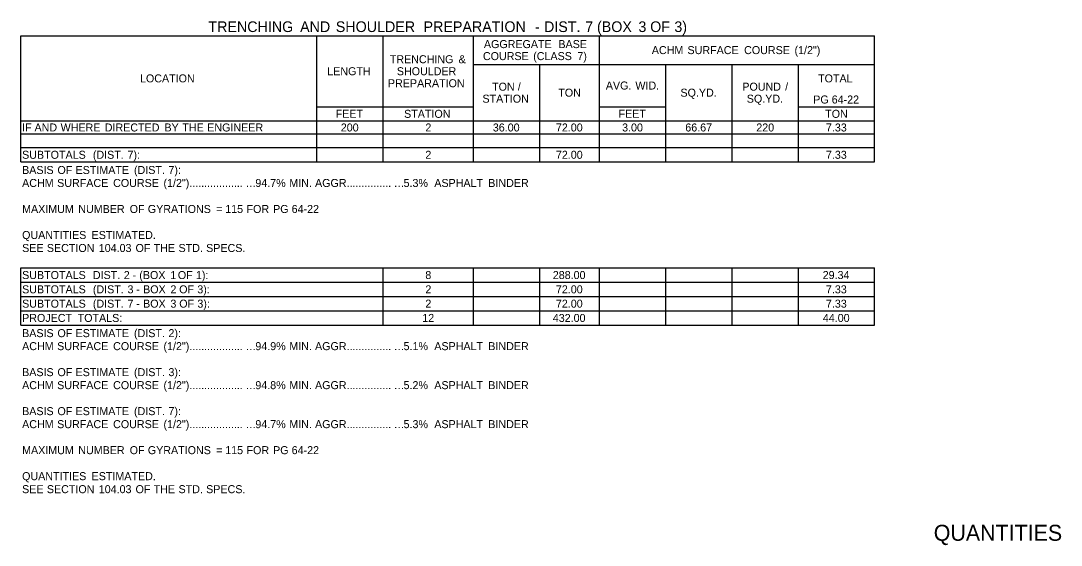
# Model space of a CAD drawing. Extents: x 544250 to 1930787, y -1948365 to 596640.
# Drawn here: x 546909 to 547689, y -1948344 to -1947951 of the extents above; entities that cross this region are included whole.
import ezdxf

# ---------------------------------------------------------------- set-up
doc = ezdxf.new("R2010")
doc.units = 0
doc.layers.add('Default', color=7, linetype='Continuous')
doc.layers.add('R_Border', color=7, linetype='Continuous')

msp = doc.modelspace()

# ---------------------------------------------------------------- linework, layer by layer
at = {"layer": 'Default'}
for p, q in [((546908.73, -1947962.26), (547548.82, -1947962.26)), ((546908.73, -1948056.83), (546908.73, -1947962.26)), ((546908.73, -1948056.83), (546908.73, -1947962.26)), ((547130.54, -1948056.83), (547130.54, -1947962.26)), ((547180.27, -1948056.83), (547180.27, -1947962.26)), ((547248.03, -1948056.83), (547248.03, -1947962.26)), ((547342.61, -1948056.83), (547342.61, -1947962.26)), ((547548.82, -1948056.83), (547548.82, -1947962.26)), ((547548.82, -1948056.83), (547548.82, -1947962.26)), ((547248.03, -1947983.71), (547548.82, -1947983.71)), ((547297.76, -1948056.83), (547297.76, -1947983.71)), ((547392.33, -1948056.83), (547392.33, -1947983.71)), ((547442.06, -1948056.83), (547442.06, -1947983.71)), ((547491.78, -1948056.83), (547491.78, -1947983.71)), ((547130.54, -1948015.4), (547248.03, -1948015.4)), ((547180.27, -1948046.11), (547180.27, -1948015.4)), ((547342.61, -1948015.4), (547392.33, -1948015.4)), ((547342.61, -1948026.12), (547342.61, -1948015.4)), ((547392.33, -1948046.11), (547392.33, -1948015.4)), ((547491.78, -1948015.4), (547548.82, -1948015.4)), ((546908.73, -1948026.12), (547491.78, -1948026.12)), ((547130.54, -1948056.83), (547130.54, -1948026.12)), ((547248.03, -1948026.12), (547392.33, -1948026.12)), ((547248.03, -1948046.11), (547248.03, -1948026.12)), ((547297.76, -1948046.11), (547297.76, -1948026.12)), ((547392.33, -1948026.12), (547548.82, -1948026.12)), ((547442.06, -1948046.11), (547442.06, -1948026.12)), ((547491.78, -1948026.12), (547548.82, -1948026.12)), ((547491.78, -1948046.11), (547491.78, -1948026.12)), ((546908.73, -1948035.87), (547548.82, -1948035.87)), ((546908.73, -1948046.11), (547548.82, -1948046.11)), ((546908.73, -1948046.11), (547548.82, -1948046.11)), ((546908.73, -1948056.83), (547548.82, -1948056.83)), ((546908.73, -1948136.3), (547548.82, -1948136.3)), ((546908.73, -1948136.3), (547548.82, -1948136.3)), ((546908.73, -1948179.2), (546908.73, -1948136.3)), ((546908.73, -1948179.2), (546908.73, -1948136.3)), ((547180.27, -1948179.2), (547180.27, -1948136.3)), ((547180.27, -1948179.2), (547180.27, -1948136.3)), ((547248.03, -1948179.2), (547248.03, -1948136.3)), ((547248.03, -1948179.2), (547248.03, -1948136.3)), ((547297.76, -1948179.2), (547297.76, -1948136.3)), ((547342.61, -1948179.2), (547342.61, -1948136.3)), ((547392.33, -1948179.2), (547392.33, -1948136.3)), ((547442.06, -1948179.2), (547442.06, -1948136.3)), ((547491.78, -1948179.2), (547491.78, -1948136.3)), ((547548.82, -1948179.2), (547548.82, -1948136.3)), ((547548.82, -1948179.2), (547548.82, -1948136.3)), ((546908.73, -1948147.02), (547548.82, -1948147.02)), ((546908.73, -1948157.75), (547548.82, -1948157.75)), ((546908.73, -1948168.47), (547548.82, -1948168.47)), ((546908.73, -1948179.2), (547548.82, -1948179.2))]:
    msp.add_line(p, q, dxfattribs=at)

# ---------------------------------------------------------------- texts
for s, height, p in [('TRENCHING', 8, (547049.37, -1947959.43)), (' AND', 8, (547115.15, -1947959.43)), (' SHOULDER', 8, (547141.92, -1947959.43)), (' PREPARATION', 8, (547207.7, -1947959.43)), (' -', 8, (547291.27, -1947959.43)), (' DIST.', 8, (547298.01, -1947959.43)), (' 7', 8, (547328.92, -1947959.43)), (' (BOX', 8, (547337.74, -1947959.43)), (' 3', 8, (547368.78, -1947959.43)), (' OF', 8, (547377.61, -1947959.43)), (' 3)', 8, (547395.72, -1947959.43)), ('AGGREGATE', 6, (547255.9, -1947971.48)), (' BASE', 6, (547309.53, -1947971.48)), ('ACHM', 6, (547381.78, -1947975.98)), (' SURFACE', 6, (547406.33, -1947975.98)), (' COURSE', 6, (547448.77, -1947975.98)), (' (1/2")', 6, (547486.55, -1947975.98)), ('TRENCHING', 6, (547185.36, -1947982.83)), (' &', 6, (547234.69, -1947982.83)), ('COURSE', 6, (547255.19, -1947980.48)), (' (CLASS', 6, (547290.65, -1947980.48)), (' 7)', 6, (547323.77, -1947980.48)), ('LENGTH', 6, (547138.49, -1947991.83)), ('SHOULDER', 6, (547190.65, -1947991.83)), ('LOCATION', 6, (546998.08, -1947997.19)), ('PREPARATION', 6, (547183.97, -1948000.83)), ('AVG.', 6, (547347.32, -1948002.55)), (' WID.', 6, (547367.24, -1948002.55)), ('TOTAL', 6, (547506.45, -1947997.19)), ('TON', 6, (547262.05, -1948003.41)), (' /', 6, (547279.07, -1948003.41)), ('TON', 6, (547311.67, -1948007.91)), ('SQ.YD.', 6, (547403.27, -1948007.91)), ('POUND', 6, (547449.66, -1948003.41)), (' /', 6, (547479.52, -1948003.41)), ('STATION', 6, (547254.83, -1948012.41)), ('SQ.YD.', 6, (547453, -1948012.41)), ('PG', 6, (547502.83, -1948013.03)), (' 64-22', 6, (547514.43, -1948013.03)), ('FEET', 6, (547144.78, -1948023.76)), ('STATION', 6, (547196.09, -1948023.76)), ('FEET', 6, (547356.84, -1948023.76)), ('TON', 6, (547511.79, -1948023.76)), ('IF', 6, (546909.71, -1948034)), (' AND', 6, (546916.77, -1948034)), (' WHERE', 6, (546936.35, -1948034)), (' DIRECTED', 6, (546969.44, -1948034)), (' BY', 6, (547014.18, -1948034)), (' THE', 6, (547027.63, -1948034)), (' ENGINEER', 6, (547046.27, -1948034)), ('200', 6, (547148.62, -1948034)), ('2', 6, (547212.04, -1948034)), ('36.00', 6, (547262.61, -1948034)), ('72.00', 6, (547309.9, -1948034)), ('3.00', 6, (547359.52, -1948034)), ('66.67', 6, (547406.9, -1948034)), ('220', 6, (547460.13, -1948034)), ('7.33', 6, (547512.34, -1948034)), ('SUBTOTALS', 6, (546909.71, -1948054.47)), (' (DIST.', 6, (546960.53, -1948054.47)), (' 7):', 6, (546986.5, -1948054.47)), ('2', 6, (547212.03, -1948054.47)), ('72.00', 6, (547309.9, -1948054.47)), ('7.33', 6, (547512.33, -1948054.47)), ('BASIS', 6, (546909.71, -1948065.87)), (' OF', 6, (546933.97, -1948065.87)), (' ESTIMATE', 6, (546947.55, -1948065.87)), (' (DIST.', 6, (546991.36, -1948065.87)), (' 7):', 6, (547017.17, -1948065.87)), ('ACHM', 6, (546909.71, -1948075.62)), (' SURFACE', 6, (546933.76, -1948075.62)), (' COURSE', 6, (546975.71, -1948075.62)), (' (1/2")..................', 6, (547013.46, -1948075.62)), ('94.7%', 6, (547084.56, -1948075.62)), (' MIN.', 6, (547107.8, -1948075.62)), (' AGGR...............', 6, (547127.09, -1948075.62)), ('5.3%', 6, (547195.69, -1948075.62)), ('  ASPHALT', 6, (547214.27, -1948075.62)), (' BINDER', 6, (547256.97, -1948075.62)), ('…', 6, (547077.16, -1948075.62)), ('…', 6, (547188.29, -1948075.62)), ('MAXIMUM', 6, (546909.71, -1948095.12)), (' NUMBER', 6, (546949.59, -1948095.12)), (' OF', 6, (546988.14, -1948095.12)), (' GYRATIONS', 6, (547001.73, -1948095.12)), (' 115', 6, (547059.75, -1948095.12)), (' FOR', 6, (547075.73, -1948095.12)), (' PG', 6, (547095.64, -1948095.12)), (' 64-22', 6, (547109.55, -1948095.12)), (' =', 6, (547053, -1948095.12)), ('QUANTITIES', 6, (546909.71, -1948114.62)), (' ESTIMATED.', 6, (546959.58, -1948114.62)), ('SEE', 6, (546909.71, -1948124.37)), (' SECTION', 6, (546926.04, -1948124.37)), (' 104.03', 6, (546964.95, -1948124.37)), (' OF', 6, (546992.52, -1948124.37)), (' THE', 6, (547006.11, -1948124.37)), (' STD.', 6, (547024.76, -1948124.37)), (' SPECS.', 6, (547045.45, -1948124.37)), ('SUBTOTALS', 6, (546909.71, -1948144.66)), (' DIST.', 6, (546960.53, -1948144.66)), (' 2', 6, (546983.71, -1948144.66)), (' -', 6, (546990.28, -1948144.66)), (' (BOX', 6, (546995.33, -1948144.66)), (' 1', 6, (547018.61, -1948144.66)), (' OF', 6, (547024.24, -1948144.66)), (' 1):', 6, (547037.82, -1948144.66)), ('8', 6, (547212.01, -1948144.66)), ('288.00', 6, (547307.57, -1948144.66)), ('29.34', 6, (547509.91, -1948144.66)), ('SUBTOTALS', 6, (546909.71, -1948155.38)), (' (DIST.', 6, (546960.53, -1948155.38)), (' 3', 6, (546986.5, -1948155.38)), (' BOX', 6, (546998.18, -1948155.38)), (' 2', 6, (547018.67, -1948155.38)), (' OF', 6, (547025.24, -1948155.38)), (' 3):', 6, (547038.82, -1948155.38)), ('2', 6, (547212.03, -1948155.38)), ('72.00', 6, (547309.9, -1948155.38)), ('7.33', 6, (547512.33, -1948155.38)), ('SUBTOTALS', 6, (546909.71, -1948166.11)), (' (DIST.', 6, (546960.53, -1948166.11)), (' 7', 6, (546986.5, -1948166.11)), (' -', 6, (546993.13, -1948155.38)), (' BOX', 6, (546998.17, -1948166.11)), (' 3', 6, (547018.66, -1948166.11)), (' OF', 6, (547025.29, -1948166.11)), (' 3):', 6, (547038.87, -1948166.11)), ('2', 6, (547212.03, -1948166.11)), ('72.00', 6, (547309.9, -1948166.11)), ('7.33', 6, (547512.33, -1948166.11)), (' -', 6, (546993.12, -1948166.11)), ('PROJECT', 6, (546909.71, -1948176.83)), (' TOTALS:', 6, (546949.13, -1948176.83)), ('12', 6, (547209.7, -1948176.83)), ('432.00', 6, (547307.57, -1948176.83)), ('44.00', 6, (547510.02, -1948176.83)), ('BASIS', 6, (546909.71, -1948188.23)), (' OF', 6, (546933.97, -1948188.23)), (' ESTIMATE', 6, (546947.55, -1948188.23)), (' (DIST.', 6, (546991.36, -1948188.23)), (' 2):', 6, (547017.17, -1948188.23)), (' (1/2")..................', 6, (547013.46, -1948197.98)), ('ACHM', 6, (546909.71, -1948197.98)), (' SURFACE', 6, (546933.76, -1948197.98)), (' COURSE', 6, (546975.71, -1948197.98)), ('…', 6, (547077.16, -1948197.98)), ('94.9%', 6, (547084.56, -1948197.98)), (' MIN.', 6, (547107.8, -1948197.98)), (' AGGR...............', 6, (547127.09, -1948197.98)), ('…', 6, (547188.29, -1948197.98)), ('5.1%', 6, (547195.69, -1948197.98)), ('  ASPHALT', 6, (547214.27, -1948197.98)), (' BINDER', 6, (547256.97, -1948197.98)), ('BASIS', 6, (546909.71, -1948217.48)), (' OF', 6, (546933.97, -1948217.48)), (' ESTIMATE', 6, (546947.55, -1948217.48)), (' (DIST.', 6, (546991.36, -1948217.48)), (' 3):', 6, (547017.17, -1948217.48)), ('ACHM', 6, (546909.71, -1948227.23)), (' SURFACE', 6, (546933.76, -1948227.23)), (' COURSE', 6, (546975.71, -1948227.23)), (' (1/2")..................', 6, (547013.46, -1948227.23)), ('94.8%', 6, (547084.56, -1948227.23)), (' MIN.', 6, (547107.8, -1948227.23)), (' AGGR...............', 6, (547127.09, -1948227.23)), ('5.2%', 6, (547195.69, -1948227.23)), ('  ASPHALT', 6, (547214.27, -1948227.23)), (' BINDER', 6, (547256.97, -1948227.23)), ('…', 6, (547077.16, -1948227.23)), ('…', 6, (547188.29, -1948227.23)), ('BASIS', 6, (546909.71, -1948246.73)), (' OF', 6, (546933.97, -1948246.73)), (' ESTIMATE', 6, (546947.55, -1948246.73)), (' (DIST.', 6, (546991.36, -1948246.73)), (' 7):', 6, (547017.17, -1948246.73)), ('ACHM', 6, (546909.71, -1948256.48)), (' SURFACE', 6, (546933.76, -1948256.48)), (' COURSE', 6, (546975.71, -1948256.48)), (' (1/2")..................', 6, (547013.46, -1948256.48)), ('94.7%', 6, (547084.56, -1948256.48)), (' MIN.', 6, (547107.8, -1948256.48)), (' AGGR...............', 6, (547127.09, -1948256.48)), ('5.3%', 6, (547195.69, -1948256.48)), ('  ASPHALT', 6, (547214.27, -1948256.48)), (' BINDER', 6, (547256.97, -1948256.48)), ('…', 6, (547077.16, -1948256.48)), ('…', 6, (547188.29, -1948256.48)), ('MAXIMUM', 6, (546909.71, -1948275.98)), (' NUMBER', 6, (546949.59, -1948275.98)), (' OF', 6, (546988.14, -1948275.98)), (' GYRATIONS', 6, (547001.73, -1948275.98)), (' =', 6, (547053, -1948275.98)), (' 115', 6, (547059.75, -1948275.98)), (' FOR', 6, (547075.73, -1948275.98)), (' PG', 6, (547095.64, -1948275.98)), (' 64-22', 6, (547109.55, -1948275.98)), ('QUANTITIES', 6, (546909.71, -1948295.48)), (' ESTIMATED.', 6, (546959.58, -1948295.48)), ('SEE', 6, (546909.71, -1948305.23)), (' SECTION', 6, (546926.04, -1948305.23)), (' 104.03', 6, (546964.95, -1948305.23)), (' OF', 6, (546992.52, -1948305.23)), (' THE', 6, (547006.11, -1948305.23)), (' STD.', 6, (547024.76, -1948305.23)), (' SPECS.', 6, (547045.45, -1948305.23))]:
    msp.add_text(s, height=height, dxfattribs=at).set_placement(p)
at = {"layer": 'R_Border'}
msp.add_text('QUANTITIES', height=12, rotation=360, dxfattribs=at).set_placement((547593.16, -1948340.95))

doc.saveas('drawing.dxf')
